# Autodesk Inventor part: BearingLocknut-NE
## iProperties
Author: Gerald L. Pierce
Shininess: 86.0
PropertySet Name: _Private Model Information
Length Units: 11272
Angle Units: 11286
Time Units: 11279
Mass Units: 11290
Length Display Precision: 4
Angle Display Precision: 2
Compacted: True
Created: 2002-11
Part Number: BearingLocknut-NE
Material: Steel, Mild
Document SubType Name: Modeling
Designer: Ole Germer
Control State: 0
Master: False
Checked Out: False
PropertySet Name: Design Tracking Control
Density: 7.859999999999999
Volumn: 32.75577793121353
Area: 116.51683115369147
PropertySet Name: Model Information
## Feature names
1. Body [Extrusion]
2. Chamfer1
3. SpannerSlot [Extrusion]
4. Circular Pattern1
5. Chamfer2
